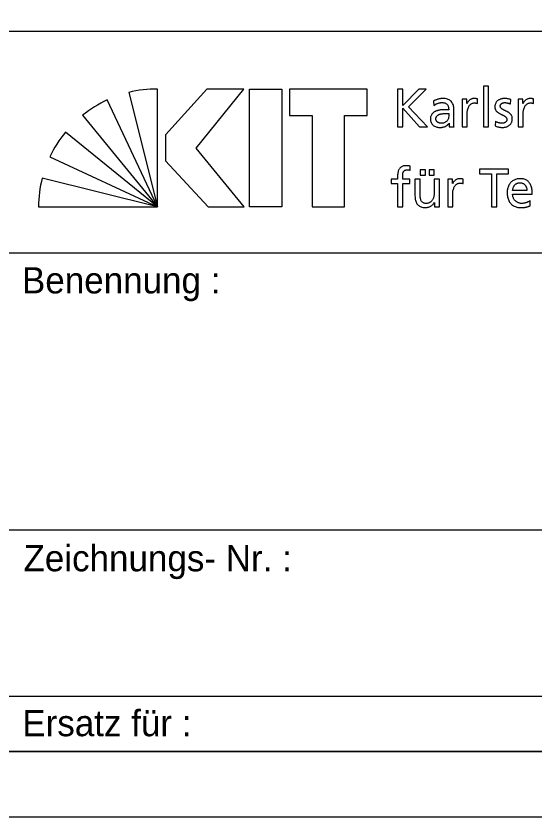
# Model space of a CAD drawing. Extents: x 0 to 14.9, y 0 to 10.5.
# Drawn here: x 12.641 to 13.633, y 0 to 1.529 of the extents above; entities that cross this region are included whole.
import ezdxf

# ---------------------------------------------------------------- set-up
doc = ezdxf.new("R2010")
doc.units = 0
doc.layers.add('90_Plankopf', color=7, linetype='Continuous')

msp = doc.modelspace()

# ---------------------------------------------------------------- linework, layer by layer
at = {"layer": '90_Plankopf'}
for p, q in [((10.278, 1.4998), (14.725, 1.4998)), ((10.278, 1.4998), (14.725, 1.4998)), ((12.8569, 1.3833), (12.912, 1.1647)), ((12.912, 1.1647), (12.912, 1.3896)), ((13.3702, 1.3897), (13.3702, 1.3176)), ((12.912, 1.1647), (12.8158, 1.3688)), ((13.4395, 1.3665), (13.44, 1.3583)), ((13.5232, 1.3621), (13.5232, 1.3708)), ((13.5864, 1.361), (13.5872, 1.3694)), ((13.6303, 1.3621), (13.6303, 1.3708)), ((13.478, 1.328), (13.478, 1.3497)), ((12.7686, 1.3396), (12.912, 1.1647)), ((13.4683, 1.3427), (13.4683, 1.3381)), ((13.3702, 1.3176), (13.3806, 1.3176)), ((13.4126, 1.3176), (13.4277, 1.3176)), ((13.5574, 1.328), (13.5569, 1.3193)), ((12.912, 1.1647), (12.7358, 1.3071)), ((12.706, 1.2603), (12.912, 1.1647)), ((13.3943, 1.2348), (13.3947, 1.2427)), ((12.912, 1.1647), (12.6914, 1.2197)), ((13.4957, 1.2091), (13.4957, 1.2178)), ((13.6177, 1.196), (13.5904, 1.196)), ((13.5904, 1.1888), (13.628, 1.1888)), ((12.6841, 1.1647), (12.912, 1.1647)), ((13.6239, 1.1668), (13.6239, 1.1765)), ((12.625, 1.0768), (14.725, 1.0768)), ((12.625, 0.548), (14.725, 0.548)), ((12.625, 0.2308), (14.725, 0.2308)), ((14.725, 0.125), (10.278, 0.125)), ((10.57, 0.125), (14.725, 0.125)), ((10.57, 0.125), (14.725, 0.125))]:
    msp.add_line(p, q, dxfattribs=at)
for points in [[(0, 0), (14.85, 0), (14.85, 10.5), (0, 10.5)], [(0.625, 10.375), (14.725, 10.375), (14.725, 0.125), (0.625, 0.125)], [(13.0767, 1.3897), (13.0059, 1.3897), (12.9268, 1.3025), (12.9268, 1.2523), (13.0084, 1.1647), (13.0771, 1.1647), (12.9856, 1.2766)], [(13.1493, 1.3897), (13.1493, 1.1647), (13.0875, 1.1647), (13.0875, 1.3897)], [(13.1641, 1.3897), (13.1641, 1.339), (13.2075, 1.339), (13.2075, 1.1647), (13.2693, 1.1647), (13.2693, 1.339), (13.3127, 1.339), (13.3127, 1.3897)]]:
    msp.add_lwpolyline(points, close=True, dxfattribs=at)
for points in [[(13.5345, 1.3176), (13.5442, 1.3176), (13.5442, 1.395), (13.5345, 1.395), (13.5345, 1.3176)], [(13.4277, 1.3176), (13.3912, 1.3556), (13.425, 1.3897), (13.4113, 1.3897), (13.3806, 1.358), (13.3806, 1.3897), (13.3702, 1.3897)], [(13.503, 1.3621), (13.5028, 1.3621), (13.5028, 1.3703), (13.4938, 1.3703), (13.4938, 1.3176), (13.5035, 1.3176), (13.5035, 1.3416)], [(13.6102, 1.3621), (13.61, 1.3621), (13.61, 1.3703), (13.6009, 1.3703), (13.6009, 1.3176), (13.6106, 1.3176), (13.6106, 1.3416)], [(13.3806, 1.3176), (13.3806, 1.3529), (13.4126, 1.3176)], [(13.4691, 1.3245), (13.4693, 1.3245), (13.4693, 1.3176), (13.4784, 1.3176)], [(13.4139, 1.2356), (13.4139, 1.2253), (13.4236, 1.2253), (13.4236, 1.2356), (13.4139, 1.2356)], [(13.4308, 1.2356), (13.4308, 1.2253), (13.4405, 1.2253), (13.4405, 1.2356), (13.4308, 1.2356)], [(13.5498, 1.1647), (13.5601, 1.1647), (13.5601, 1.2276), (13.5825, 1.2276), (13.5825, 1.2367), (13.5274, 1.2367), (13.5274, 1.2276), (13.5498, 1.2276), (13.5498, 1.1647)], [(13.3706, 1.2221), (13.3706, 1.2173), (13.3582, 1.2173), (13.3582, 1.2094), (13.3706, 1.2094), (13.3706, 1.1647), (13.3803, 1.1647), (13.3803, 1.2094), (13.3942, 1.2094), (13.3942, 1.2173), (13.3803, 1.2173), (13.3803, 1.223)], [(13.4135, 1.19), (13.4135, 1.2173), (13.4038, 1.2173), (13.4038, 1.186)], [(13.4504, 1.1647), (13.4504, 1.2173), (13.4407, 1.2173), (13.4407, 1.1929)], [(13.4756, 1.2091), (13.4754, 1.2091), (13.4754, 1.2173), (13.4663, 1.2173), (13.4663, 1.1647), (13.476, 1.1647), (13.476, 1.1886)], [(13.4408, 1.173), (13.441, 1.173), (13.441, 1.1647), (13.4504, 1.1647)]]:
    msp.add_lwpolyline(points, dxfattribs=at)
for centre, start, end in [((12.9112, 1.1514), 89.8053, 103.1895), ((12.9165, 1.1529), 115.0126, 128.3968), ((12.9204, 1.1566), 140.7898, 154.174), ((12.9223, 1.1609), 165.7222, 179.1064)]:
    msp.add_arc(centre, 0.2382, start, end, dxfattribs=at)
for points in [[(13.478, 1.3497), (13.478, 1.3545), (13.4773, 1.3585), (13.4758, 1.3617), (13.4744, 1.365), (13.4721, 1.3674), (13.469, 1.369), (13.4659, 1.3707), (13.4618, 1.3715), (13.4568, 1.3715), (13.4535, 1.3715), (13.4503, 1.371), (13.4474, 1.3701), (13.4445, 1.3692), (13.4419, 1.368), (13.4395, 1.3665)], [(13.44, 1.3583), (13.4413, 1.3594), (13.4428, 1.3604), (13.4445, 1.3611), (13.4461, 1.362), (13.4479, 1.3626), (13.4497, 1.363), (13.4516, 1.3634), (13.4534, 1.3637), (13.4553, 1.3637), (13.4585, 1.3637), (13.461, 1.3631), (13.4629, 1.3621), (13.4649, 1.3611), (13.4662, 1.3596), (13.467, 1.3575), (13.4679, 1.3555), (13.4683, 1.353), (13.4683, 1.3499)], [(13.5232, 1.3708), (13.5225, 1.3709), (13.5218, 1.371), (13.5212, 1.3712), (13.5206, 1.3713), (13.5199, 1.3713), (13.5192, 1.3714), (13.5185, 1.3715), (13.5177, 1.3715), (13.5168, 1.3715), (13.5149, 1.3715), (13.5131, 1.3711), (13.5113, 1.3703), (13.5095, 1.3695), (13.5079, 1.3684), (13.5065, 1.367), (13.5051, 1.3656), (13.5039, 1.3639), (13.503, 1.3621)], [(13.5035, 1.3416), (13.5035, 1.346), (13.5041, 1.3498), (13.5052, 1.353), (13.5064, 1.3562), (13.5081, 1.3587), (13.5102, 1.3604), (13.5124, 1.3621), (13.5149, 1.363), (13.5178, 1.363), (13.5186, 1.3631), (13.5195, 1.363), (13.5204, 1.3629), (13.5214, 1.3627), (13.5223, 1.3625), (13.5232, 1.3621)], [(13.5872, 1.3694), (13.5854, 1.37), (13.5834, 1.3705), (13.5815, 1.3709), (13.5795, 1.3713), (13.5774, 1.3715), (13.5752, 1.3715), (13.5726, 1.3715), (13.5701, 1.3712), (13.5679, 1.3705), (13.5656, 1.3698), (13.5637, 1.3688), (13.562, 1.3675), (13.5603, 1.3662), (13.559, 1.3645), (13.558, 1.3625), (13.5571, 1.3604), (13.5566, 1.358), (13.5566, 1.3553), (13.5566, 1.3532), (13.5571, 1.3514), (13.5579, 1.3498), (13.5587, 1.3483), (13.5598, 1.347), (13.5611, 1.3459), (13.5625, 1.3447), (13.564, 1.3437), (13.5656, 1.3429), (13.5672, 1.342), (13.5688, 1.3412), (13.5704, 1.3404), (13.5721, 1.3397), (13.5735, 1.3389), (13.5749, 1.338), (13.5762, 1.3373), (13.5773, 1.3363), (13.5782, 1.3353), (13.579, 1.3343), (13.5794, 1.3331), (13.5794, 1.3318), (13.5794, 1.3304), (13.5791, 1.3292), (13.5785, 1.3282), (13.5779, 1.3272), (13.5771, 1.3265), (13.5761, 1.3259), (13.5751, 1.3253), (13.5741, 1.3249), (13.5729, 1.3246), (13.5718, 1.3244), (13.5706, 1.3242), (13.5695, 1.3242), (13.5685, 1.3242), (13.5674, 1.3244), (13.566, 1.3247), (13.5646, 1.3249), (13.5631, 1.3253), (13.5616, 1.3259), (13.5601, 1.3265), (13.5587, 1.3271), (13.5574, 1.328)], [(13.5569, 1.3193), (13.5592, 1.3181), (13.5615, 1.3174), (13.5639, 1.317), (13.5664, 1.3166), (13.5689, 1.3164), (13.5714, 1.3164), (13.5737, 1.3164), (13.576, 1.3167), (13.5782, 1.3174), (13.5804, 1.318), (13.5823, 1.3191), (13.5841, 1.3204), (13.5858, 1.3217), (13.5872, 1.3234), (13.5882, 1.3255), (13.5892, 1.3276), (13.5897, 1.33), (13.5897, 1.3328), (13.5897, 1.3352), (13.5893, 1.3372), (13.5885, 1.3389), (13.5876, 1.3406), (13.5866, 1.342), (13.5852, 1.3431), (13.5839, 1.3443), (13.5824, 1.3453), (13.5807, 1.3461), (13.5791, 1.3469), (13.5775, 1.3477), (13.5759, 1.3484), (13.5743, 1.3491), (13.5728, 1.3499), (13.5714, 1.3507), (13.5701, 1.3515), (13.569, 1.3524), (13.5682, 1.3534), (13.5674, 1.3545), (13.5669, 1.3557), (13.5669, 1.3573), (13.5669, 1.3587), (13.5674, 1.3599), (13.5682, 1.3609), (13.5691, 1.3618), (13.5702, 1.3625), (13.5716, 1.363), (13.573, 1.3634), (13.5745, 1.3637), (13.5762, 1.3637), (13.5768, 1.3637), (13.5776, 1.3636), (13.5785, 1.3634), (13.5794, 1.3633), (13.5803, 1.3631), (13.5814, 1.3628), (13.5824, 1.3626), (13.5833, 1.3623), (13.5842, 1.362), (13.5851, 1.3616), (13.5859, 1.3613), (13.5864, 1.361)], [(13.6303, 1.3708), (13.6296, 1.3709), (13.629, 1.371), (13.6284, 1.3712), (13.6277, 1.3713), (13.6271, 1.3713), (13.6264, 1.3714), (13.6257, 1.3715), (13.6248, 1.3715), (13.6239, 1.3715), (13.622, 1.3715), (13.6202, 1.3711), (13.6184, 1.3703), (13.6167, 1.3695), (13.6151, 1.3684), (13.6136, 1.367), (13.6122, 1.3656), (13.611, 1.3639), (13.6102, 1.3621)], [(13.6106, 1.3416), (13.6106, 1.346), (13.6112, 1.3498), (13.6124, 1.353), (13.6136, 1.3562), (13.6152, 1.3587), (13.6173, 1.3604), (13.6195, 1.3621), (13.622, 1.363), (13.6249, 1.363), (13.6258, 1.3631), (13.6266, 1.363), (13.6276, 1.3629), (13.6285, 1.3627), (13.6294, 1.3625), (13.6303, 1.3621)], [(13.4683, 1.3499), (13.467, 1.35), (13.4658, 1.3501), (13.4647, 1.3501), (13.4636, 1.3501), (13.4626, 1.3501), (13.4615, 1.3501), (13.4604, 1.3501), (13.4592, 1.3501), (13.4579, 1.3501), (13.4559, 1.3501), (13.4538, 1.35), (13.4516, 1.3496), (13.4493, 1.3492), (13.4471, 1.3487), (13.445, 1.3478), (13.4429, 1.347), (13.441, 1.346), (13.4392, 1.3446), (13.4375, 1.3433), (13.4361, 1.3416), (13.4351, 1.3397), (13.434, 1.3377), (13.4335, 1.3354), (13.4335, 1.3328), (13.4335, 1.329), (13.4344, 1.3259), (13.436, 1.3235), (13.4376, 1.3211), (13.4399, 1.3193), (13.4427, 1.3181), (13.4456, 1.317), (13.449, 1.3164), (13.4528, 1.3164), (13.455, 1.3164), (13.457, 1.3167), (13.4588, 1.3172), (13.4605, 1.3177), (13.4621, 1.3184), (13.4634, 1.3192), (13.4648, 1.32), (13.4659, 1.3209), (13.4668, 1.3218), (13.4678, 1.3228), (13.4685, 1.3236), (13.4691, 1.3245)], [(13.4683, 1.3381), (13.4683, 1.3354), (13.4677, 1.3331), (13.4666, 1.331), (13.4655, 1.3289), (13.4638, 1.3273), (13.4617, 1.3261), (13.4595, 1.3249), (13.4568, 1.3243), (13.4536, 1.3242), (13.4525, 1.3242), (13.4514, 1.3244), (13.4502, 1.3248), (13.4491, 1.3252), (13.448, 1.3257), (13.447, 1.3264), (13.4461, 1.3272), (13.4453, 1.3281), (13.4447, 1.3291), (13.4441, 1.3302), (13.4438, 1.3314), (13.4438, 1.3328), (13.4438, 1.3347), (13.4443, 1.3362), (13.4452, 1.3374), (13.4461, 1.3387), (13.4473, 1.3396), (13.4487, 1.3404), (13.4502, 1.3411), (13.4517, 1.3417), (13.4534, 1.342), (13.455, 1.3424), (13.4566, 1.3426), (13.4582, 1.3428), (13.4597, 1.3429), (13.461, 1.3429), (13.4621, 1.3429), (13.4631, 1.3429), (13.4641, 1.3429), (13.4652, 1.3428), (13.4662, 1.3428), (13.4672, 1.3427), (13.4683, 1.3427)], [(13.4784, 1.3176), (13.4783, 1.3181), (13.4782, 1.3188), (13.4782, 1.3197), (13.4781, 1.3205), (13.4781, 1.3216), (13.478, 1.323), (13.478, 1.3243), (13.478, 1.326), (13.478, 1.328)], [(13.3947, 1.2427), (13.3938, 1.2428), (13.3928, 1.243), (13.3917, 1.2431), (13.3906, 1.2432), (13.3895, 1.2433), (13.3882, 1.2433), (13.3847, 1.2433), (13.3818, 1.2428), (13.3794, 1.2418), (13.3771, 1.2408), (13.3753, 1.2394), (13.3741, 1.2375), (13.3728, 1.2356), (13.3719, 1.2334), (13.3714, 1.2308), (13.3708, 1.2282), (13.3706, 1.2253), (13.3706, 1.2221)], [(13.3803, 1.223), (13.3803, 1.2247), (13.3804, 1.2264), (13.3806, 1.2279), (13.3808, 1.2294), (13.3812, 1.2307), (13.3819, 1.2319), (13.3825, 1.233), (13.3835, 1.2339), (13.3847, 1.2345), (13.386, 1.2351), (13.3876, 1.2354), (13.3897, 1.2354), (13.3905, 1.2354), (13.3914, 1.2354), (13.3922, 1.2353), (13.393, 1.2352), (13.3938, 1.235), (13.3943, 1.2348)], [(13.4957, 1.2178), (13.495, 1.2179), (13.4943, 1.2181), (13.4938, 1.2182), (13.4931, 1.2183), (13.4925, 1.2184), (13.4917, 1.2184), (13.4911, 1.2185), (13.4902, 1.2185), (13.4893, 1.2185), (13.4874, 1.2185), (13.4856, 1.2181), (13.4838, 1.2173), (13.4821, 1.2165), (13.4805, 1.2154), (13.479, 1.214), (13.4776, 1.2126), (13.4764, 1.211), (13.4756, 1.2091)], [(13.476, 1.1886), (13.476, 1.193), (13.4766, 1.1968), (13.4778, 1.2), (13.4789, 1.2032), (13.4806, 1.2057), (13.4827, 1.2074), (13.4849, 1.2092), (13.4874, 1.21), (13.4903, 1.21), (13.4912, 1.2101), (13.492, 1.21), (13.493, 1.2099), (13.4939, 1.2097), (13.4948, 1.2095), (13.4957, 1.2091)], [(13.628, 1.1888), (13.628, 1.1931), (13.6276, 1.197), (13.6268, 1.2006), (13.626, 1.2042), (13.6247, 1.2073), (13.6229, 1.21), (13.6211, 1.2127), (13.6188, 1.2148), (13.6158, 1.2162), (13.6128, 1.2177), (13.6091, 1.2185), (13.6047, 1.2185), (13.601, 1.2185), (13.5976, 1.2178), (13.5946, 1.2166), (13.5916, 1.2152), (13.589, 1.2134), (13.5868, 1.2111), (13.5847, 1.2087), (13.583, 1.2059), (13.5819, 1.2026), (13.5807, 1.1994), (13.5801, 1.1958), (13.5801, 1.1919), (13.5801, 1.1876), (13.5806, 1.1837), (13.5817, 1.1802), (13.5828, 1.1767), (13.5845, 1.1737), (13.5867, 1.1712), (13.5889, 1.1687), (13.5918, 1.1668), (13.5952, 1.1655), (13.5986, 1.1641), (13.6027, 1.1634), (13.6073, 1.1634), (13.6102, 1.1634), (13.6126, 1.1636), (13.6147, 1.164), (13.6167, 1.1644), (13.6184, 1.1648), (13.6199, 1.1653), (13.6214, 1.1659), (13.6227, 1.1664), (13.6239, 1.1668)], [(13.5904, 1.196), (13.5906, 1.1977), (13.591, 1.1995), (13.5916, 1.2012), (13.5922, 1.2029), (13.5931, 1.2045), (13.5942, 1.2059), (13.5953, 1.2073), (13.5967, 1.2085), (13.5984, 1.2093), (13.6001, 1.2102), (13.6022, 1.2107), (13.6045, 1.2107), (13.6066, 1.2107), (13.6085, 1.2103), (13.6101, 1.2095), (13.6117, 1.2088), (13.6131, 1.2077), (13.6142, 1.2064), (13.6153, 1.205), (13.6162, 1.2035), (13.6168, 1.2017), (13.6174, 1.1999), (13.6177, 1.1981), (13.6177, 1.196)], [(13.4407, 1.1929), (13.4407, 1.1897), (13.4404, 1.1868), (13.4397, 1.1841), (13.4391, 1.1815), (13.4381, 1.1792), (13.4368, 1.1773), (13.4355, 1.1754), (13.4338, 1.1739), (13.4318, 1.1728), (13.4298, 1.1718), (13.4274, 1.1713), (13.4247, 1.1713), (13.4219, 1.1714), (13.4197, 1.1722), (13.418, 1.1736), (13.4164, 1.175), (13.4152, 1.1771), (13.4145, 1.1798), (13.4139, 1.1825), (13.4135, 1.1859), (13.4135, 1.19)], [(13.4038, 1.186), (13.4038, 1.1813), (13.4045, 1.1772), (13.4059, 1.1739), (13.4073, 1.1705), (13.4095, 1.1679), (13.4124, 1.1661), (13.4153, 1.1644), (13.419, 1.1634), (13.4236, 1.1634), (13.426, 1.1634), (13.4284, 1.1638), (13.4306, 1.1646), (13.4329, 1.1653), (13.4349, 1.1665), (13.4367, 1.1679), (13.4384, 1.1693), (13.4398, 1.171), (13.4408, 1.173)], [(13.6239, 1.1765), (13.6233, 1.176), (13.6225, 1.1755), (13.6213, 1.1749), (13.6202, 1.1743), (13.6189, 1.1737), (13.6174, 1.1732), (13.6159, 1.1726), (13.6143, 1.1722), (13.6126, 1.1718), (13.611, 1.1715), (13.6094, 1.1713), (13.6077, 1.1713), (13.6054, 1.1713), (13.6032, 1.1717), (13.6012, 1.1725), (13.5991, 1.1734), (13.5972, 1.1746), (13.5956, 1.1761), (13.594, 1.1777), (13.5927, 1.1795), (13.5918, 1.1817), (13.5909, 1.1838), (13.5904, 1.1862), (13.5904, 1.1888)]]:
    msp.add_open_spline(points, degree=3, dxfattribs=at)

# ---------------------------------------------------------------- texts
for s, p in [('Benennung :', (12.6528, 0.9995)), ('Zeichnungs- Nr. :', (12.6557, 0.469)), ('Ersatz für :', (12.6535, 0.1542))]:
    msp.add_text(s, height=0.05, dxfattribs=at).set_placement(p)

doc.saveas('drawing.dxf')
